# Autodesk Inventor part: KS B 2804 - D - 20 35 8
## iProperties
IsCustomPart: 0
Created: 2009-02
Part Number: KS B 2804 - D - 20 35 8
Material: 고무
Description: 오일-실
Document SubType Name: Modeling
Standard: KS B 2804
Designer: SeoGD™ [www.esajin.kr]
Standards Organization: KS
Language: ko-KR
Size Designation: D - 20 35 8
Categories: <MemberInstance><Categories><Category DisplayName="샤프트 부품" InternalName="7f7aeb1f-a693-4053-b835-cee3144e0d98" Mnemonic="SHFT"><Category DisplayName="실링" Intern
Density: 0.93 g/cm^3
Author: SeoGD™ [www.esajin.kr]
